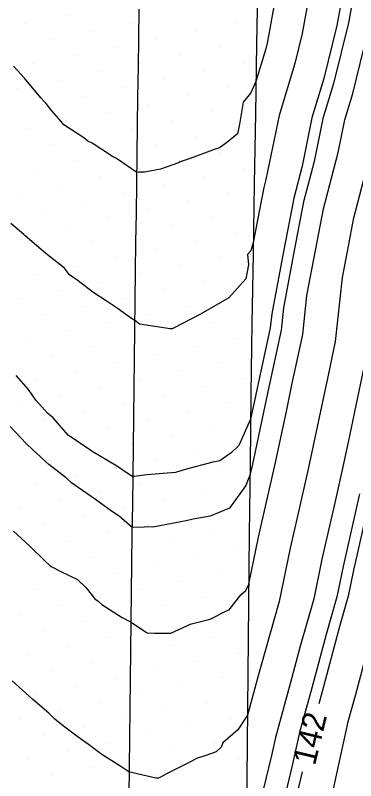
# Model space of a CAD drawing. Extents: x 2354170 to 2357230, y 866100 to 868290.
# Drawn here: x 2355345.9 to 2355375.1, y 866883.7 to 866949.4 of the extents above; entities that cross this region are included whole.
import ezdxf

# ---------------------------------------------------------------- set-up
doc = ezdxf.new("R2010")
doc.units = 0
for name, color, linetype in [('Default', 7, 'Continuous'), ('DTM Contours Minor', 7, 'Continuous'), ('Exist DTM Breakline', 7, 'Continuous'), ('Exist DTM Scan Elevation Point', 7, 'Continuous'), ('Exist Roads EOP', 7, 'Continuous')]:
    doc.layers.add(name, color=color, linetype=linetype)

msp = doc.modelspace()

# ---------------------------------------------------------------- linework, layer by layer
at = {"layer": 'Default'}
for points in [[(2355368.477, 866952.508), (2355367.515, 866947.119), (2355367.361, 866946.498), (2355366.525, 866943.698), (2355366.075, 866942.726), (2355365.419, 866941.927), (2355365.073, 866939.87), (2355364.946, 866939.198), (2355364.001, 866938.429), (2355363.384, 866938.008), (2355363.037, 866937.899), (2355360.884, 866937.091), (2355360.123, 866936.829), (2355360.025, 866936.788), (2355359.876, 866936.724), (2355358.349, 866936.159), (2355356.959, 866935.925), (2355356.482, 866935.906), (2355356.317, 866935.881), (2355355.02, 866936.759), (2355354.554, 866937.077), (2355354.238, 866937.264), (2355352.482, 866938.389), (2355352.108, 866938.575), (2355351.775, 866938.844), (2355350.042, 866939.983), (2355349.815, 866940.249), (2355349.013, 866941.182), (2355348.551, 866941.795), (2355348.359, 866941.971), (2355348.078, 866942.3), (2355346.677, 866943.959), (2355345.724, 866944.998)], [(2355371.221, 866951.912), (2355370.488, 866947.809), (2355369.845, 866945.22), (2355368.515, 866940.767), (2355367.381, 866935.279), (2355367.206, 866934.605), (2355366.295, 866929.894), (2355366.077, 866929.16), (2355365.803, 866928.852), (2355365.886, 866927.958), (2355365.642, 866926.782), (2355364.203, 866925.136), (2355364.195, 866925.129), (2355361.772, 866923.748), (2355359.505, 866922.57), (2355359.333, 866922.468), (2355359.164, 866922.475), (2355356.548, 866922.879), (2355356.147, 866923.198), (2355355.78, 866923.416), (2355354.623, 866924.254), (2355353.774, 866924.818), (2355352.531, 866925.622), (2355351.274, 866926.605), (2355350.524, 866927.12), (2355350.098, 866927.678), (2355348.654, 866928.824), (2355348.319, 866929.12), (2355346.735, 866930.455), (2355346.616, 866930.577), (2355345.496, 866931.518)], [(2355373.964, 866951.316), (2355373.461, 866948.498), (2355372.33, 866943.942), (2355371.326, 866940.582), (2355370.47, 866936.44), (2355369.757, 866933.687), (2355368.872, 866929.113), (2355367.876, 866923.777), (2355367.747, 866922.576), (2355366.546, 866917.006), (2355366.484, 866916.711), (2355366.066, 866914.735), (2355365.055, 866912.47), (2355364.399, 866911.845), (2355363.437, 866911.173), (2355362.838, 866911.052), (2355360.458, 866910.418), (2355359.638, 866910.171), (2355357.163, 866909.968), (2355356.064, 866909.81), (2355355.983, 866909.756), (2355355.955, 866909.787), (2355355.878, 866909.845), (2355355.39, 866910.166), (2355354.644, 866910.668), (2355354.634, 866910.678), (2355354.502, 866910.756), (2355352.488, 866911.965), (2355352.446, 866911.994), (2355350.41, 866913.355), (2355349.134, 866914.853), (2355348.66, 866915.241), (2355347.664, 866916.358), (2355347.016, 866917.286), (2355345.958, 866918.471)], [(2355385.984, 866950.01), (2355385.316, 866944.67), (2355383.664, 866940.01), (2355382.563, 866937.423), (2355379.976, 866930.073), (2355379.961, 866930.015), (2355379.959, 866930.008), (2355379.958, 866930.001), (2355378.907, 866920.234), (2355378.802, 866919.747), (2355377.07, 866911.453), (2355376.808, 866910.213), (2355376.468, 866908.733), (2355374.893, 866901.784), (2355374.434, 866899.575), (2355373.666, 866896.841), (2355372.256, 866891.59), (2355371.905, 866890.322)], [(2355345.746, 866905.143), (2355347.124, 866903.857), (2355348.428, 866902.599), (2355348.888, 866902.175), (2355348.967, 866902.112), (2355349.804, 866901.689), (2355351.225, 866900.994), (2355351.956, 866900.266), (2355352.723, 866899.348), (2355352.99, 866899.13), (2355353.317, 866898.859), (2355355.064, 866897.734), (2355355.76, 866897.356), (2355355.819, 866897.325), (2355357.149, 866896.439), (2355357.2, 866896.432), (2355357.823, 866896.384), (2355359.231, 866896.392), (2355360.588, 866897.022), (2355360.877, 866897.168), (2355361.104, 866897.211), (2355362.598, 866897.578), (2355363.988, 866898.3), (2355364.234, 866898.402), (2355365.226, 866899.669), (2355365.666, 866900.042), (2355365.903, 866900.592), (2355366.742, 866904.628), (2355366.882, 866905.246), (2355368.151, 866910.768), (2355369.131, 866915.397), (2355369.61, 866917.691), (2355370.537, 866921.991), (2355370.897, 866925.333), (2355371.644, 866929.337), (2355372.308, 866932.769), (2355373.559, 866937.6), (2355374.137, 866940.396), (2355374.814, 866942.665), (2355376.434, 866949.188)], [(2355376.647, 866938.76), (2355374.859, 866931.851), (2355374.416, 866929.561), (2355373.917, 866926.889), (2355373.327, 866921.405), (2355372.674, 866918.377), (2355371.777, 866914.082), (2355371.036, 866910.583), (2355370.077, 866906.408), (2355369.459, 866903.68), (2355368.509, 866899.112), (2355366.922, 866893.455), (2355366.725, 866892.723), (2355365.798, 866889.372), (2355364.977, 866888.107), (2355363.669, 866886.975), (2355363.541, 866886.605), (2355363.105, 866886.23), (2355362.233, 866885.916), (2355361.421, 866885.641), (2355360.913, 866885.347), (2355358.968, 866884.383), (2355358.331, 866884.058), (2355358.157, 866883.952), (2355357.947, 866883.969), (2355355.843, 866884.448), (2355355.665, 866884.478), (2355355.457, 866884.612), (2355355.028, 866884.898), (2355353.296, 866886), (2355352.154, 866886.852), (2355351.267, 866887.465), (2355350.031, 866888.416), (2355349.29, 866889.008), (2355348.774, 866889.523), (2355347.408, 866890.693), (2355345.631, 866892.308)], [(2355375.738, 866919.062), (2355374.424, 866912.767), (2355373.922, 866910.398), (2355373.272, 866907.571), (2355372.176, 866902.732), (2355371.471, 866899.344), (2355370.294, 866895.148), (2355369.491, 866892.157), (2355368.184, 866887.433), (2355367.846, 866885.901), (2355366.621, 866880.85)], [(2355377.039, 866898.535), (2355375.022, 866891.024), (2355374.404, 866888.792), (2355373.194, 866883.303), (2355372.509, 866880.479), (2355371.607, 866877.027), (2355370.751, 866873.165), (2355369.685, 866869.221), (2355368.47, 866864.364), (2355367.971, 866862.414), (2355366.438, 866857.129), (2355366.271, 866856.498), (2355365.315, 866852.302), (2355364.978, 866851.696), (2355364.442, 866850.923), (2355363.379, 866849.453)], [(2355370.493, 866884.492), (2355369.565, 866880.665)]]:
    msp.add_lwpolyline(points, dxfattribs=at)
at = {"layer": 'DTM Contours Minor'}
for points in [[(2355374.879, 866951.117), (2355374.452, 866948.728), (2355373.158, 866943.516), (2355372.263, 866940.52), (2355371.499, 866936.826), (2355370.608, 866933.381), (2355369.796, 866929.188), (2355368.883, 866924.295), (2355368.677, 866922.381), (2355367.567, 866917.234), (2355367.367, 866916.273), (2355366.227, 866910.892), (2355366.005, 866909.924), (2355365.655, 866909.046), (2355364.265, 866907.11), (2355364.263, 866907.108), (2355362.602, 866906.414), (2355361.144, 866906.177), (2355360.539, 866906.01), (2355357.679, 866905.472), (2355357.214, 866905.515), (2355356.935, 866905.473), (2355355.929, 866905.443), (2355355.69, 866905.655), (2355354.808, 866906.409), (2355354.126, 866906.85), (2355352.771, 866907.861), (2355351.274, 866908.891), (2355350.71, 866909.277), (2355350.293, 866909.677), (2355348.757, 866910.856), (2355348.474, 866911.111), (2355346.897, 866912.575), (2355346.814, 866912.66), (2355345.443, 866914.102)], [(2355375.403, 866908.346), (2355373.987, 866902.1), (2355373.446, 866899.498), (2355372.542, 866896.277), (2355371.334, 866891.779), (2355370.257, 866887.886), (2355369.629, 866885.035), (2355368.584, 866880.727)]]:
    msp.add_lwpolyline(points, dxfattribs=at)
at = {"layer": 'Exist DTM Breakline'}
msp.add_lwpolyline([(2355355.639, 866882.402), (2355355.67, 866884.902), (2355355.699, 866887.402), (2355355.728, 866889.902), (2355355.757, 866892.402), (2355355.786, 866894.902), (2355355.82, 866897.401), (2355355.854, 866899.901), (2355355.889, 866902.401), (2355355.922, 866904.901), (2355355.954, 866907.4), (2355355.985, 866909.9), (2355356.016, 866912.4), (2355356.047, 866914.9), (2355356.077, 866917.4), (2355356.107, 866919.899), (2355356.137, 866922.399), (2355356.167, 866924.899), (2355356.201, 866927.399), (2355356.235, 866929.899), (2355356.269, 866932.398), (2355356.303, 866934.898), (2355356.339, 866937.398), (2355356.374, 866939.898), (2355356.41, 866942.397), (2355356.445, 866944.897), (2355356.481, 866947.397), (2355356.518, 866949.897)], dxfattribs=at)
at = {"layer": 'Exist DTM Scan Elevation Point'}
for p, q in [((2355350.249, 866949.357), (2355350.249, 866949.357)), ((2355355.798, 866948.683), (2355355.798, 866948.683)), ((2355364.812, 866948.715), (2355364.812, 866948.715)), ((2355346.784, 866948.652), (2355346.784, 866948.652)), ((2355352.333, 866947.978), (2355352.333, 866947.978)), ((2355361.347, 866948.009), (2355361.347, 866948.009)), ((2355348.869, 866947.272), (2355348.869, 866947.272)), ((2355357.883, 866947.304), (2355357.883, 866947.304)), ((2355354.418, 866946.598), (2355354.418, 866946.598)), ((2355363.432, 866946.63), (2355363.432, 866946.63)), ((2355350.954, 866945.893), (2355350.954, 866945.893)), ((2355359.968, 866945.924), (2355359.968, 866945.924)), ((2355347.49, 866945.187), (2355347.49, 866945.187)), ((2355356.503, 866945.219), (2355356.503, 866945.219)), ((2355365.517, 866945.251), (2355365.517, 866945.251)), ((2355353.039, 866944.513), (2355353.039, 866944.513)), ((2355362.053, 866944.545), (2355362.053, 866944.545)), ((2355349.575, 866943.808), (2355349.575, 866943.808)), ((2355358.588, 866943.839), (2355358.588, 866943.839)), ((2355346.11, 866943.102), (2355346.11, 866943.102)), ((2355355.124, 866943.134), (2355355.124, 866943.134)), ((2355364.138, 866943.166), (2355364.138, 866943.166)), ((2355351.66, 866942.428), (2355351.66, 866942.428)), ((2355360.673, 866942.46), (2355360.673, 866942.46)), ((2355348.195, 866941.723), (2355348.195, 866941.723)), ((2355357.209, 866941.755), (2355357.209, 866941.755)), ((2355353.745, 866941.049), (2355353.745, 866941.049)), ((2355362.758, 866941.081), (2355362.758, 866941.081)), ((2355350.28, 866940.343), (2355350.28, 866940.343)), ((2355359.294, 866940.375), (2355359.294, 866940.375)), ((2355346.816, 866939.638), (2355346.816, 866939.638)), ((2355355.83, 866939.67), (2355355.83, 866939.67)), ((2355364.843, 866939.701), (2355364.843, 866939.701)), ((2355352.365, 866938.964), (2355352.365, 866938.964)), ((2355361.379, 866938.996), (2355361.379, 866938.996)), ((2355348.901, 866938.258), (2355348.901, 866938.258)), ((2355357.915, 866938.29), (2355357.915, 866938.29)), ((2355354.45, 866937.585), (2355354.45, 866937.585)), ((2355363.464, 866937.616), (2355363.464, 866937.616)), ((2355350.986, 866936.879), (2355350.986, 866936.879)), ((2355360, 866936.911), (2355360, 866936.911)), ((2355365.549, 866936.237), (2355365.549, 866936.237)), ((2355347.521, 866936.173), (2355347.521, 866936.173)), ((2355356.535, 866936.205), (2355356.535, 866936.205)), ((2355353.071, 866935.5), (2355353.071, 866935.5)), ((2355362.085, 866935.531), (2355362.085, 866935.531)), ((2355349.606, 866934.794), (2355349.606, 866934.794)), ((2355358.62, 866934.826), (2355358.62, 866934.826)), ((2355346.142, 866934.088), (2355346.142, 866934.088)), ((2355355.156, 866934.12), (2355355.156, 866934.12)), ((2355364.17, 866934.152), (2355364.17, 866934.152)), ((2355351.691, 866933.415), (2355351.691, 866933.415)), ((2355360.705, 866933.446), (2355360.705, 866933.446)), ((2355348.227, 866932.709), (2355348.227, 866932.709)), ((2355357.241, 866932.741), (2355357.241, 866932.741)), ((2355353.776, 866932.035), (2355353.776, 866932.035)), ((2355362.79, 866932.067), (2355362.79, 866932.067)), ((2355350.312, 866931.33), (2355350.312, 866931.33)), ((2355359.326, 866931.361), (2355359.326, 866931.361)), ((2355346.847, 866930.624), (2355346.847, 866930.624)), ((2355355.861, 866930.656), (2355355.861, 866930.656)), ((2355364.875, 866930.687), (2355364.875, 866930.687)), ((2355352.397, 866929.95), (2355352.397, 866929.95)), ((2355361.411, 866929.982), (2355361.411, 866929.982)), ((2355348.932, 866929.245), (2355348.932, 866929.245)), ((2355357.946, 866929.276), (2355357.946, 866929.276)), ((2355354.482, 866928.571), (2355354.482, 866928.571)), ((2355363.496, 866928.602), (2355363.496, 866928.602)), ((2355351.017, 866927.865), (2355351.017, 866927.865)), ((2355360.031, 866927.897), (2355360.031, 866927.897)), ((2355347.553, 866927.16), (2355347.553, 866927.16)), ((2355356.567, 866927.191), (2355356.567, 866927.191)), ((2355365.581, 866927.223), (2355365.581, 866927.223)), ((2355353.102, 866926.486), (2355353.102, 866926.486)), ((2355362.116, 866926.517), (2355362.116, 866926.517)), ((2355349.638, 866925.78), (2355349.638, 866925.78)), ((2355358.652, 866925.812), (2355358.652, 866925.812)), ((2355346.174, 866925.075), (2355346.174, 866925.075)), ((2355355.187, 866925.106), (2355355.187, 866925.106)), ((2355364.201, 866925.138), (2355364.201, 866925.138)), ((2355351.723, 866924.401), (2355351.723, 866924.401)), ((2355360.737, 866924.432), (2355360.737, 866924.432)), ((2355348.259, 866923.695), (2355348.259, 866923.695)), ((2355357.272, 866923.727), (2355357.272, 866923.727)), ((2355353.808, 866923.021), (2355353.808, 866923.021)), ((2355362.822, 866923.053), (2355362.822, 866923.053)), ((2355350.344, 866922.316), (2355350.344, 866922.316)), ((2355359.357, 866922.347), (2355359.357, 866922.347)), ((2355346.879, 866921.61), (2355346.879, 866921.61)), ((2355355.893, 866921.642), (2355355.893, 866921.642)), ((2355364.907, 866921.674), (2355364.907, 866921.674)), ((2355352.429, 866920.936), (2355352.429, 866920.936)), ((2355361.442, 866920.968), (2355361.442, 866920.968)), ((2355348.964, 866920.231), (2355348.964, 866920.231)), ((2355357.978, 866920.262), (2355357.978, 866920.262)), ((2355354.514, 866919.557), (2355354.514, 866919.557)), ((2355363.527, 866919.589), (2355363.527, 866919.589)), ((2355351.049, 866918.851), (2355351.049, 866918.851)), ((2355360.063, 866918.883), (2355360.063, 866918.883)), ((2355347.585, 866918.146), (2355347.585, 866918.146)), ((2355356.599, 866918.177), (2355356.599, 866918.177)), ((2355365.612, 866918.209), (2355365.612, 866918.209)), ((2355353.134, 866917.472), (2355353.134, 866917.472)), ((2355362.148, 866917.504), (2355362.148, 866917.504)), ((2355349.67, 866916.766), (2355349.67, 866916.766)), ((2355358.683, 866916.798), (2355358.683, 866916.798)), ((2355346.205, 866916.061), (2355346.205, 866916.061)), ((2355355.219, 866916.092), (2355355.219, 866916.092)), ((2355364.233, 866916.124), (2355364.233, 866916.124)), ((2355351.755, 866915.387), (2355351.755, 866915.387)), ((2355360.768, 866915.419), (2355360.768, 866915.419)), ((2355348.29, 866914.681), (2355348.29, 866914.681)), ((2355357.304, 866914.713), (2355357.304, 866914.713)), ((2355353.84, 866914.007), (2355353.84, 866914.007)), ((2355362.853, 866914.039), (2355362.853, 866914.039)), ((2355350.375, 866913.302), (2355350.375, 866913.302)), ((2355359.389, 866913.334), (2355359.389, 866913.334)), ((2355346.911, 866912.596), (2355346.911, 866912.596)), ((2355355.925, 866912.628), (2355355.925, 866912.628)), ((2355364.938, 866912.66), (2355364.938, 866912.66)), ((2355361.474, 866911.954), (2355361.474, 866911.954)), ((2355352.46, 866911.923), (2355352.46, 866911.923)), ((2355348.996, 866911.217), (2355348.996, 866911.217)), ((2355358.01, 866911.249), (2355358.01, 866911.249)), ((2355354.545, 866910.543), (2355354.545, 866910.543)), ((2355363.559, 866910.575), (2355363.559, 866910.575)), ((2355351.081, 866909.838), (2355351.081, 866909.838)), ((2355360.095, 866909.869), (2355360.095, 866909.869)), ((2355347.616, 866909.132), (2355347.616, 866909.132)), ((2355356.63, 866909.164), (2355356.63, 866909.164)), ((2355365.644, 866909.195), (2355365.644, 866909.195)), ((2355353.166, 866908.458), (2355353.166, 866908.458)), ((2355362.18, 866908.49), (2355362.18, 866908.49)), ((2355349.701, 866907.753), (2355349.701, 866907.753)), ((2355358.715, 866907.784), (2355358.715, 866907.784)), ((2355346.237, 866907.047), (2355346.237, 866907.047)), ((2355355.251, 866907.079), (2355355.251, 866907.079)), ((2355364.265, 866907.11), (2355364.265, 866907.11)), ((2355351.786, 866906.373), (2355351.786, 866906.373)), ((2355360.8, 866906.405), (2355360.8, 866906.405)), ((2355348.322, 866905.668), (2355348.322, 866905.668)), ((2355357.336, 866905.699), (2355357.336, 866905.699)), ((2355353.871, 866904.994), (2355353.871, 866904.994)), ((2355362.885, 866905.025), (2355362.885, 866905.025)), ((2355350.407, 866904.288), (2355350.407, 866904.288)), ((2355359.421, 866904.32), (2355359.421, 866904.32)), ((2355346.942, 866903.583), (2355346.942, 866903.583)), ((2355355.956, 866903.614), (2355355.956, 866903.614)), ((2355364.97, 866903.646), (2355364.97, 866903.646)), ((2355352.492, 866902.909), (2355352.492, 866902.909)), ((2355361.506, 866902.94), (2355361.506, 866902.94)), ((2355349.027, 866902.203), (2355349.027, 866902.203)), ((2355358.041, 866902.235), (2355358.041, 866902.235)), ((2355354.577, 866901.529), (2355354.577, 866901.529)), ((2355363.591, 866901.561), (2355363.591, 866901.561)), ((2355351.112, 866900.824), (2355351.112, 866900.824)), ((2355360.126, 866900.855), (2355360.126, 866900.855)), ((2355356.662, 866900.15), (2355356.662, 866900.15)), ((2355347.648, 866900.118), (2355347.648, 866900.118)), ((2355362.211, 866899.476), (2355362.211, 866899.476)), ((2355353.197, 866899.444), (2355353.197, 866899.444)), ((2355349.733, 866898.739), (2355349.733, 866898.739)), ((2355358.747, 866898.77), (2355358.747, 866898.77)), ((2355346.269, 866898.033), (2355346.269, 866898.033)), ((2355355.282, 866898.065), (2355355.282, 866898.065)), ((2355364.296, 866898.097), (2355364.296, 866898.097)), ((2355351.818, 866897.359), (2355351.818, 866897.359)), ((2355360.832, 866897.391), (2355360.832, 866897.391)), ((2355348.354, 866896.654), (2355348.354, 866896.654)), ((2355357.367, 866896.685), (2355357.367, 866896.685)), ((2355353.903, 866895.98), (2355353.903, 866895.98)), ((2355362.917, 866896.012), (2355362.917, 866896.012)), ((2355350.439, 866895.274), (2355350.439, 866895.274)), ((2355359.452, 866895.306), (2355359.452, 866895.306)), ((2355346.974, 866894.569), (2355346.974, 866894.569)), ((2355355.988, 866894.6), (2355355.988, 866894.6)), ((2355365.002, 866894.632), (2355365.002, 866894.632)), ((2355352.524, 866893.895), (2355352.524, 866893.895)), ((2355361.537, 866893.927), (2355361.537, 866893.927)), ((2355349.059, 866893.189), (2355349.059, 866893.189)), ((2355358.073, 866893.221), (2355358.073, 866893.221)), ((2355354.609, 866892.515), (2355354.609, 866892.515)), ((2355363.622, 866892.547), (2355363.622, 866892.547)), ((2355351.144, 866891.81), (2355351.144, 866891.81)), ((2355360.158, 866891.842), (2355360.158, 866891.842)), ((2355347.68, 866891.104), (2355347.68, 866891.104)), ((2355356.694, 866891.136), (2355356.694, 866891.136)), ((2355353.229, 866890.43), (2355353.229, 866890.43)), ((2355362.243, 866890.462), (2355362.243, 866890.462)), ((2355349.765, 866889.725), (2355349.765, 866889.725)), ((2355358.779, 866889.757), (2355358.779, 866889.757)), ((2355346.3, 866889.019), (2355346.3, 866889.019)), ((2355355.314, 866889.051), (2355355.314, 866889.051)), ((2355364.328, 866889.083), (2355364.328, 866889.083)), ((2355351.85, 866888.345), (2355351.85, 866888.345)), ((2355360.864, 866888.377), (2355360.864, 866888.377)), ((2355357.399, 866887.672), (2355357.399, 866887.672)), ((2355348.385, 866887.64), (2355348.385, 866887.64)), ((2355362.949, 866886.998), (2355362.949, 866886.998)), ((2355353.935, 866886.966), (2355353.935, 866886.966)), ((2355350.47, 866886.26), (2355350.47, 866886.26)), ((2355359.484, 866886.292), (2355359.484, 866886.292)), ((2355347.006, 866885.555), (2355347.006, 866885.555)), ((2355356.02, 866885.587), (2355356.02, 866885.587)), ((2355365.033, 866885.618), (2355365.033, 866885.618)), ((2355352.555, 866884.881), (2355352.555, 866884.881)), ((2355361.569, 866884.913), (2355361.569, 866884.913)), ((2355349.091, 866884.175), (2355349.091, 866884.175)), ((2355358.105, 866884.207), (2355358.105, 866884.207))]:
    msp.add_line(p, q, dxfattribs=at)
at = {"layer": 'Exist Roads EOP'}
msp.add_lwpolyline([(2355366.671, 866952.9), (2355366.577, 866946.901), (2355366.479, 866940.902), (2355366.378, 866934.903), (2355366.279, 866928.904), (2355366.183, 866922.904), (2355366.094, 866916.905), (2355366.016, 866910.905), (2355365.947, 866904.906), (2355365.885, 866898.906), (2355365.83, 866892.906), (2355365.776, 866886.907), (2355365.721, 866880.907), (2355365.659, 866874.907), (2355365.588, 866868.908), (2355365.503, 866862.908), (2355365.403, 866856.909), (2355365.288, 866850.91), (2355365.159, 866844.912)], dxfattribs=at)

# ---------------------------------------------------------------- texts
at = {"layer": 'Default'}
msp.add_text('142', height=2, rotation=76.38608, dxfattribs=at).set_placement((2355371.578, 866884.974))

doc.saveas('drawing.dxf')
